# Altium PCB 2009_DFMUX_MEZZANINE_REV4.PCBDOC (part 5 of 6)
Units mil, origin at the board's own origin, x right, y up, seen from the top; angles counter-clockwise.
Board outline 4922.86 x 3627.76 mil, 6 copper layers (Top Layer, Internal Plane 1, Mid-Layer 1, Internal Plane 2, Mid-Layer 2, Bottom Layer); 519 components, 606 nets, 2175 pads, 757 vias.
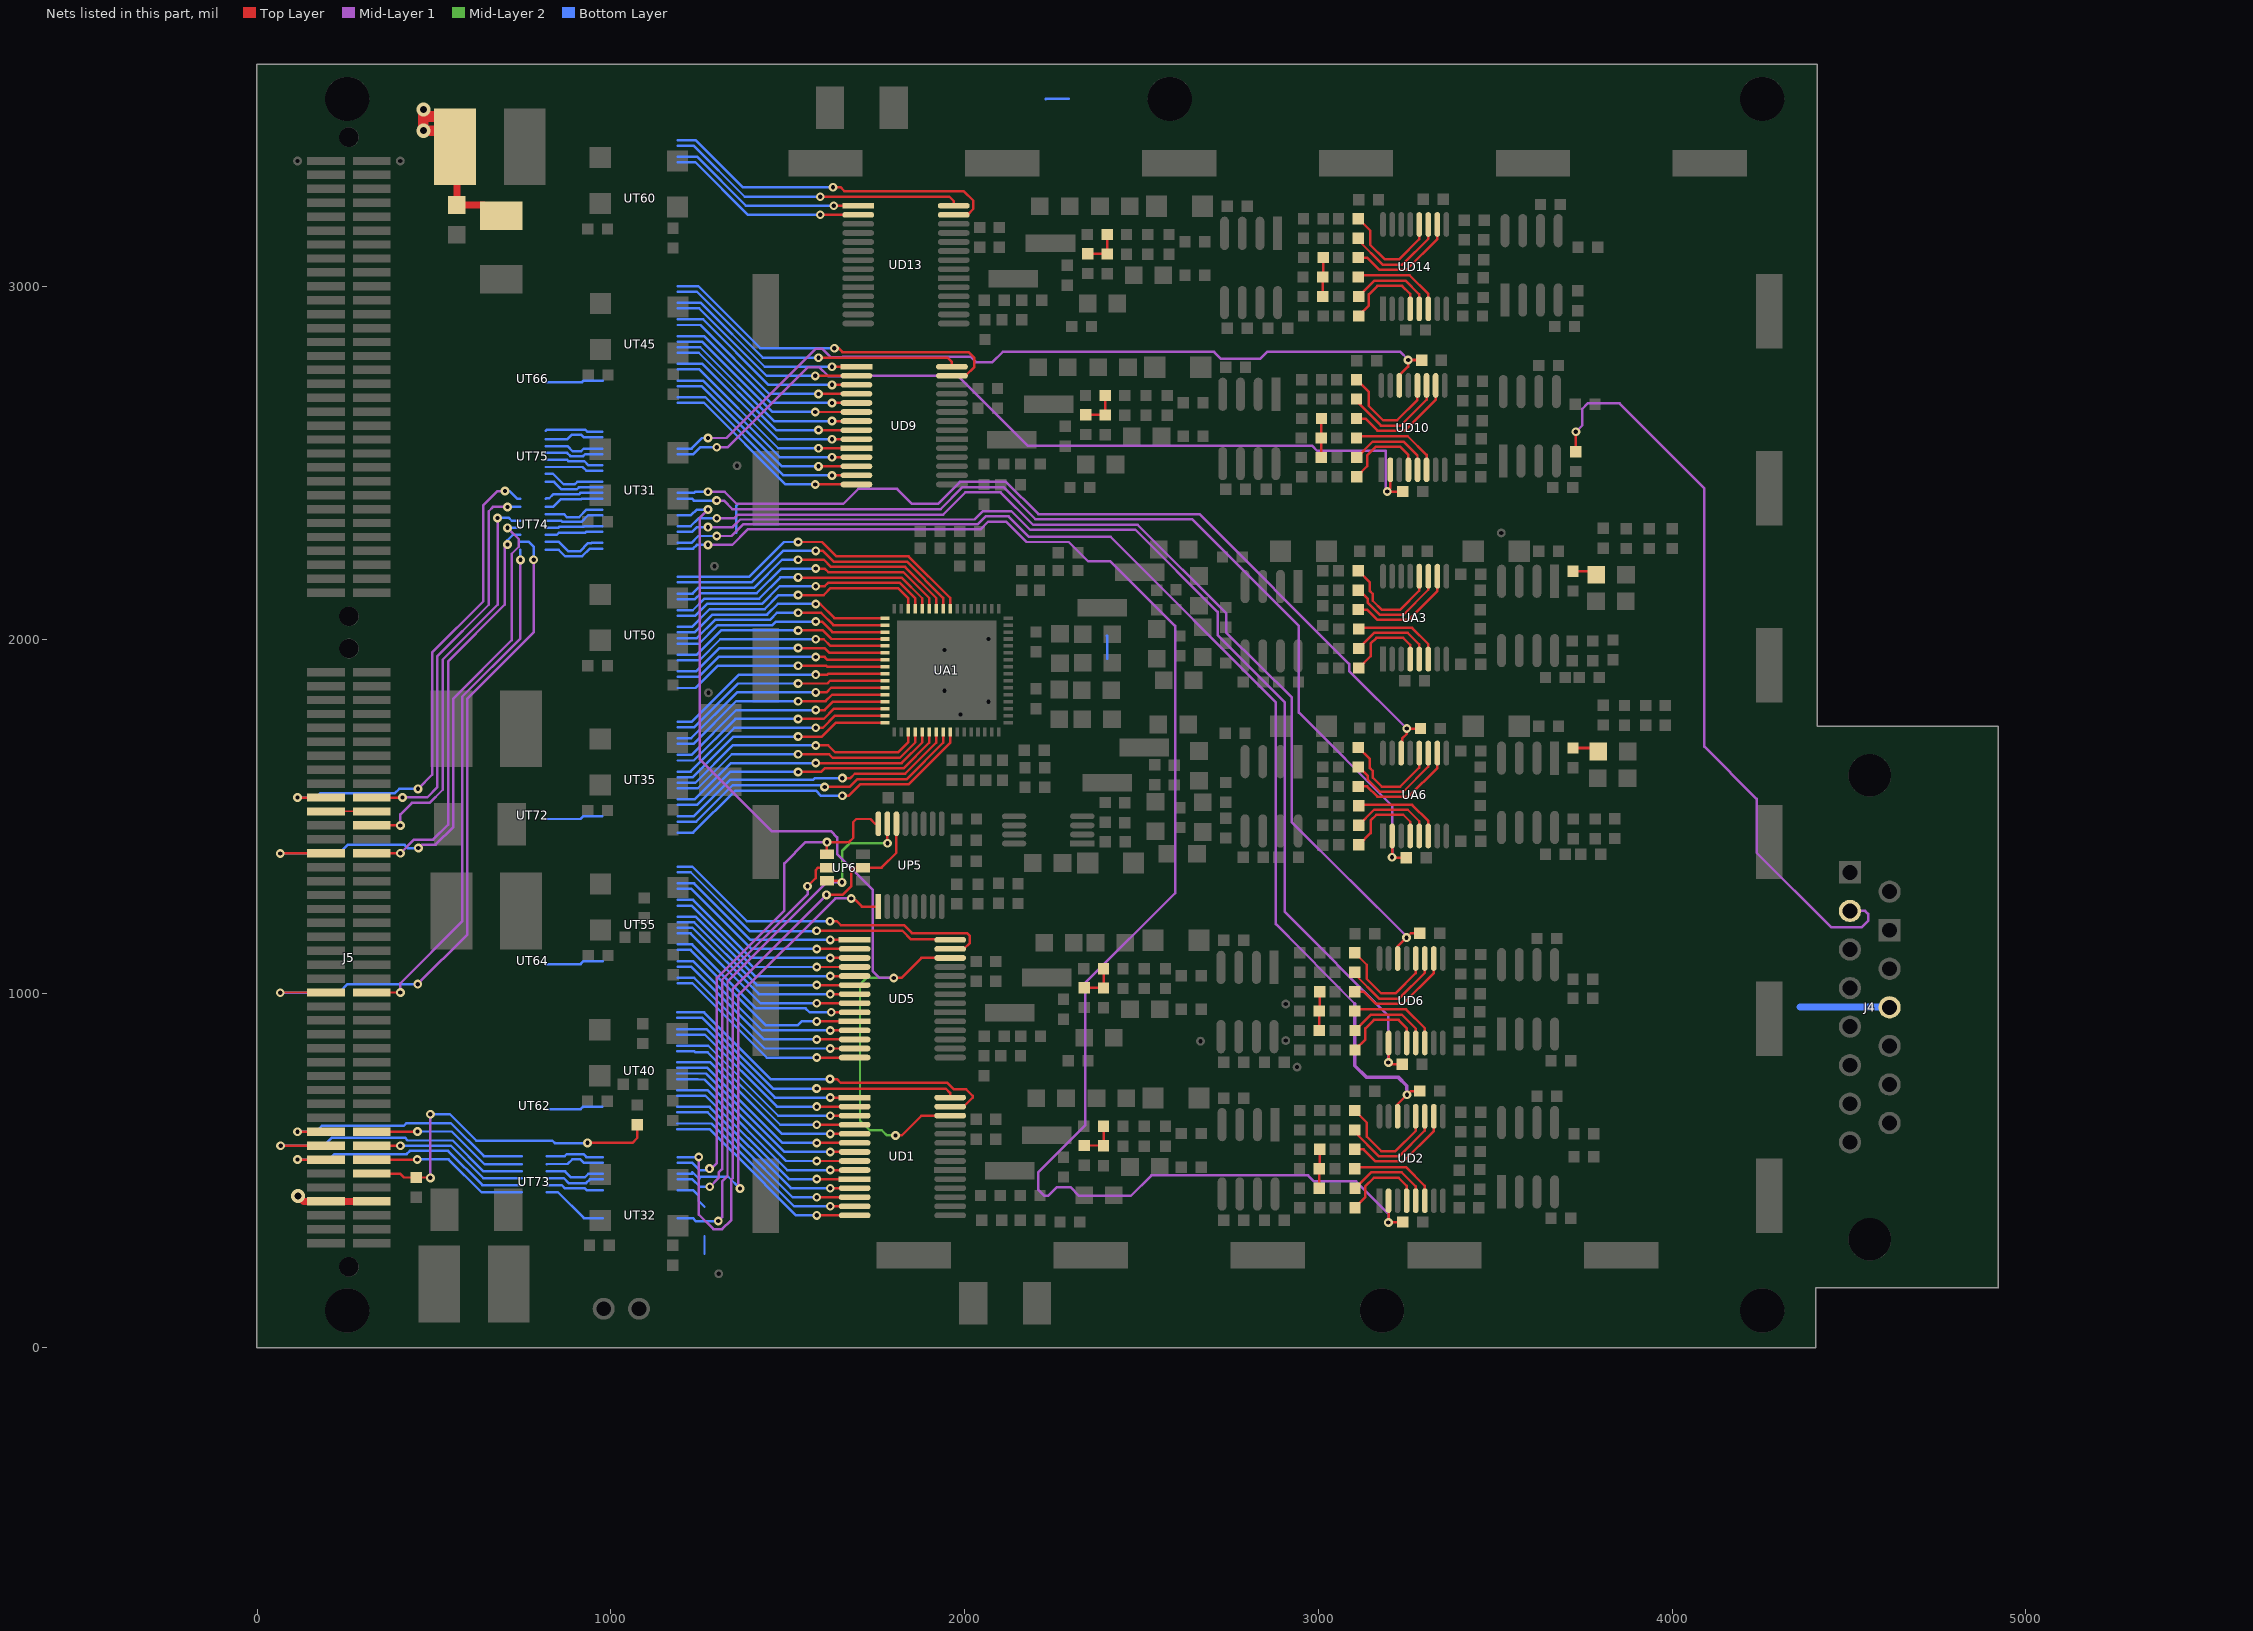
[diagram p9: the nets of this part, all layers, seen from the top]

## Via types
v1: diameter 25, hole 12, Top Layer to Bottom Layer, 692 vias
v2: diameter 40, hole 20, Top Layer to Bottom Layer, 39 vias
v3: diameter 35, hole 20, Top Layer to Bottom Layer, 23 vias
v4: diameter 22, hole 12, Top Layer to Bottom Layer, 3 vias

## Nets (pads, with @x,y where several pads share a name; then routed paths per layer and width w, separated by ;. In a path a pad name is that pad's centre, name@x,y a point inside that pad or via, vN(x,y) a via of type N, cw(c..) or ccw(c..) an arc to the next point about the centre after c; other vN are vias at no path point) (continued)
N840871_10471: UT45.30 UT66.5 | length 163.7
  Bottom Layer w7: UT66.5@815.13,2728.37 918.63,2728.37 923.03,2732.77 UT45.30@977.03,2732.77
N840871_10667: UT55.30 UT64.5 | length 165.4
  Bottom Layer w7: UT64.5@815.13,1083.37 914.63,1083.37 923.03,1091.77 UT55.30@977.03,1091.77
N840871_10863: UT40.30 UT62.5 | length 157.6
  Bottom Layer w7: UT62.5@820.13,673.37 914.63,673.37 921.03,679.77 UT40.30@975.03,679.77
N840871_11255: UT35.30 UT72.5 | length 164.4
  Bottom Layer w7: UT72.5@815.13,1493.37 913.63,1493.37 922.03,1501.77 UT35.30@976.03,1501.77
N867949: J5.19 UT74.16 | length 1439.7
  Top Layer w7: v1(114.33,1554.07) J5.19@194.63,1554.07
  Mid-Layer 1 w7: v1(454.63,1578.57) 494.63,1618.57 494.63,1964 639.63,2109 639.63,2381 679,2420.37 v1(700.63,2420.37)
  Bottom Layer w7: v1(114.33,1554.07) 166.13,1554.07 178.63,1566.57 389.63,1566.57 401.63,1578.57 v1(454.63,1578.57) ; v1(700.63,2420.37) 713.63,2420.37 735.63,2398.37 UT74.16@744.13,2398.37
N869068: J5.20 UT74.15 | length 1132.4
  Top Layer w7: J5.20@324.55,1554.07 410.93,1554.07 v1(410.63,1554.37)
  Mid-Layer 1 w7: v1(410.63,1554.37) 411.1,1554.83 481.1,1554.83 509.63,1583.37 509.63,1954 654.63,2099 654.63,2363.37 666.63,2375.37 v1(707.63,2375.37)
  Bottom Layer w7: v1(707.63,2375.37) UT74.15@744.13,2375.37
N870193: RA31.2 UA6.14 UT31.13 | length 2553
  Top Layer w7: UA6.14@3233.82,1679.68 3236.63,1682.5 3236.63,1721 3249.63,1734 v1(3249.63,1749) RA31.2@3288.63,1749
  Mid-Layer 1 w7: v1(1274.27,2418.37) 1321.27,2418.37 1355.63,2384 1656.86,2384 1699.27,2426.41 1809.27,2426.41 1851.68,2384 1924.36,2384 1986.77,2446.41 2116.77,2446.41 2208.18,2355 2663.63,2355 3086.63,1932 3086.63,1912 v1(3249.63,1749)
  Bottom Layer w7: UT31.13@1188.63,2414.97 1235.53,2414.97 1239.13,2418.37 v1(1274.27,2418.37)
N871887: RA55.2 UA6.2 UT31.14 | length 2821.3
  Top Layer w7: UA6.2@3208.23,1445.43 v1(3208.23,1385.4) 3209.63,1384 RA55.2@3248.63,1384
  Mid-Layer 1 w7: v1(1299,2393.37) 1319.27,2393.37 1343.63,2369 1931.86,2369 1994.27,2431.41 2109.27,2431.41 2199.68,2341 2643,2341 2945,2039.37 2945,1794 3208.63,1530 3208.63,1385.8 v1(3208.23,1385.4)
  Bottom Layer w7: UT31.14@1188.63,2399.27 1228.73,2399.27 1234.63,2393.37 v1(1299,2393.37)
N888717: UD1.26 UD5.26 UT31.17 | length 2741.6
  Top Layer w7: v1(1799.63,1044) 1821.27,1044 1877.9,1100.63 UD5.26@1959.03,1100.63 ; v1(1804.63,599) 1822.27,599 1877.9,654.63 UD1.26@1959.03,654.63
  Mid-Layer 1 w7: v1(1274.63,2368) 1250.63,2344 1250.63,1662.55 1454.27,1458.91 1621.77,1458.91 1639.27,1441.41 1639.27,1394.36 1739.63,1294 1739.63,1064 1759.27,1044 v1(1799.63,1044)
  Mid-Layer 2 w7: v1(1799.63,1044) 1722.25,1044 1704.13,1025.88 1704.13,640.5 1731.63,613.5 1765.5,613.5 1780,599 v1(1804.63,599)
  Bottom Layer w7: UT31.17@1188.63,2352.17 1226.3,2352.17 1242.93,2368 v1(1274.63,2368)
N890448: J5.24 UT74.13 | length 1160.3
  Top Layer w7: J5.24@324.55,1475.33 v1(404.85,1475.33)
  Mid-Layer 1 w7: v1(404.85,1475.33) 404.85,1506.22 437.63,1539 487.63,1539 524.63,1576 524.63,1944 679.63,2099 v1(679.63,2344.37)
  Bottom Layer w7: v1(679.63,2344.37) 711.63,2344.37 719.63,2336.37 UT74.13@744.13,2336.37
N891610: RD31.2 UD6.14 UT31.19 | length 2972.9
  Top Layer w7: UD6.14@3223.8,1099.02 3223.8,1133.17 v1(3248.63,1158) 3261.07,1170.43 RD31.2@3286.63,1170.43
  Mid-Layer 1 w7: v1(1299.27,2343.37) 1348,2343.37 1358.63,2354 1939.36,2354 2001.77,2416.41 2101.77,2416.41 2193.18,2325 2488.63,2325 2739.63,2074 2739.63,2019.37 2925,1836.37 2925,1484 3248.63,1162 v1(3248.63,1158)
  Bottom Layer w7: UT31.19@1188.63,2320.77 1225.4,2320.77 1248,2343.37 v1(1299.27,2343.37)
N892778: RD59.2 UD6.2 UT31.20 | length 3239
  Top Layer w7: v1(3197.63,805) v1@3198.23,804.4 ; UD6.2@3198.23,860.43 v1@3198.23,804.4 ; RD59.2@3236.63,800.43 3202.2,800.43 v1@3198.23,804.4
  Mid-Layer 1 w7: v1(1274.27,2318.37) 1344,2318.37 1365.63,2340 2027.86,2340 2051.77,2363.91 2131.77,2363.91 2184.68,2311 2482.63,2311 2715,2078.63 2715,2014 2905,1822.37 2905,1231 3197.63,936 3197.63,807 3196.63,806 v1(3197.63,805)
  Bottom Layer w7: UT31.20@1188.63,2305.07 1229.7,2305.07 1243,2318.37 v1(1274.27,2318.37)
N895125: RD1.2 UD2.14 UT31.22 | length 3382.3
  Top Layer w7: UD2.14@3223.8,653.02 3223.8,687.17 v1(3250.63,714) ; RD1.2@3286.63,724.43 3261.07,724.43 ; v1(3250.63,714) 3261.07,724.43 ; v1(3250.63,714) 3261.07,724.43
  Mid-Layer 1 w7: v1(1299.27,2293.37) 1341,2293.37 1373.63,2326 2036.36,2326 2059.27,2348.91 2124.27,2348.91 2182.18,2291 2413,2291 2880,1822.37 2880,1196.23 3102.63,971.23
  Mid-Layer 1 w10: 3102.63,971.23 3102.63,796.37 3135,764 3225,764 3250,739 3250,714.63 v1(3250.63,714)
  Bottom Layer w7: UT31.22@1188.63,2273.67 1227.53,2273.67 1246.83,2293.37 v1(1299.27,2293.37)
N896305: RD29.2 UD2.2 UT31.23 | length 4530.2
  Top Layer w7: v1(3197.63,353) 3198.03,352.6 v1@3198.23,352.6 ; UD2.2@3198.23,414.43 v1@3198.23,352.6 ; RD29.2@3238.63,355 RD29.2@3238.63,354 3199.63,354 v1@3198.23,352.6
  Mid-Layer 1 w7: v1(1274.27,2268.37) 1343,2268.37 1386.63,2312 2044.86,2312 2066.77,2333.91 2116.77,2333.91 2174.27,2276.41 2294.36,2276.41 2349.27,2221.5 2412.13,2221.5 2594.63,2039 2594.63,1283.63 2340.63,1029.63 2340.63,627 2207.63,494 2207.63,446 2225.63,428 2235.63,428 2260.63,453 2298.63,453 2323.63,428 2469.63,428 2527.63,486 2970.63,486 2987.63,469 3106.63,469 3198.63,377 3198.63,354 v1(3197.63,353)
  Bottom Layer w7: UT31.23@1188.63,2257.97 1232.6,2257.97 1243,2268.37 v1(1274.27,2268.37)
N906454: J5.27 UT74.12 | length 1628.9
  Top Layer w7: v1(65.55,1395.83) 66.32,1396.6 J5.27@194.63,1396.6
  Mid-Layer 1 w7: v1(455.73,1411.27) 455.9,1411.27 465.63,1421 504.63,1421 554.63,1471 554.63,1834 719.63,1999 719.63,2243.13 739.63,2262.93 739.63,2284.37 v1(707.63,2316.37)
  Bottom Layer w7: v1(65.55,1395.83) 231.2,1395.83 255.63,1420.27 416.63,1420.27 425.63,1411.27 v1(455.73,1411.27) ; v1(707.63,2316.37) UT74.12@744.13,2316.37
N908856: J5.28 UT74.11 | length 1165.1
  Top Layer w7: J5.28@324.55,1396.6 v1(404.85,1396.6)
  Mid-Layer 1 w7: v1(404.85,1396.6) 443.25,1435 497.63,1435 539.63,1477 539.63,1939 699.63,2099 699.63,2261.37 v1(707.63,2269.37)
  Bottom Layer w7: v1(707.63,2269.37) 707.63,2281.37 722.63,2296.37 UT74.11@744.13,2296.37
N958957: J5.47 UT74.10 | length 1943.7
  Top Layer w7: v1(65.55,1002.17) 66.32,1002.93 J5.47@194.63,1002.93
  Mid-Layer 1 w7: v1(453.87,1026.6) 594.63,1167.37 594.63,1834 781.63,2021 v1(781.63,2226.37)
  Bottom Layer w7: v1(65.55,1002.17) 231.2,1002.17 255.63,1026.6 v1(453.87,1026.6) ; UT74.10@744.13,2277.37 767.63,2277.37 781.63,2263.37 v1(781.63,2226.37)
N960349: J5.48 UT74.9 | length 1472.3
  Top Layer w7: J5.48@324.55,1002.93 v1(404.85,1002.93)
  Mid-Layer 1 w7: v1(404.85,1002.93) 404.85,1029.22 579.63,1204 579.63,1839 744.13,2003.5 v1(744.13,2225.87)
  Bottom Layer w7: v1(744.13,2225.87) UT74.9@744.13,2254.37
N995552: J5.74 RP1.1 RP4.1 | length 1012.3
  Top Layer w7: J5.74@324.55,491.17 403.47,491.17 414.63,480 RP4.1@449.63,480 488.63,480 v1(489.63,479) ; v1(933.63,578) 1060.63,578 1074.63,592 RP1.1@1074.63,629
  Mid-Layer 1 w7: v1(489.63,479) v1(489.63,659)
  Bottom Layer w7: v1(489.63,659) 544.63,659 619.63,584 834.63,584 841.63,577 932.63,577 v1(933.63,578)
N1002964: CP12.1 J5.77 J5.78 LP3.1 RP13.1 | length 738.8
  Top Layer w7: LP3.1@559.63,3394 LP3.1@564.63,3389 ; CP12.1@640.63,3229 671.63,3198 688.63,3198 CP12.1@689.63,3199
  Top Layer w10: LP3.1@514.63,3439 LP3.1@559.63,3394
  Top Layer w20: v2(115.7,427.82) 131.08,412.43 J5.77@194.63,412.43 J5.78@324.55,412.43 ; LP3.1@564.63,3389 RP13.1@564.63,3229 CP12.1@640.63,3229
  Top Layer w30: v2(470,3499) 470,3479 ; LP3.1@514.63,3439 v2(470,3439) 470,3479 ; LP3.1@520,3479 470,3479
N1115828: UP5.15 UP6.6 UT32.13 | length 1573.1
  Top Layer w7: UP6.6@1610.67,1318.37 1649.63,1318.37 v1(1653.63,1314.37) ; UP5.15@1781.52,1480.05 1781.52,1424.48 1781.63,1424.37 v1(1781.63,1425)
  Mid-Layer 1 w7: v1(1303.63,357) 1314.63,368 1314.63,469 1329.63,484 1329.63,1034 1610.63,1315 1652.63,1315 1653.63,1314 v1(1653.63,1314.37)
  Mid-Layer 2 w7: v1(1653.63,1314.37) 1653.63,1403.27 1675.36,1425 v1(1781.63,1425)
  Bottom Layer w7: UT32.13@1189.63,364.97 1231.67,364.97 1239.63,357 v1(1303.63,357)
N1144411: UT32.36 UT73.6 | length 188.3
  Bottom Layer w7: UT73.6@819.13,438.37 850.27,438.37 923.67,364.97 UT32.36@977.03,364.97
N1162483: UT32.47 UT73.1 | length 163.7
  Bottom Layer w7: UT73.1@819.13,540.37 869.63,540.37 875.27,546 922.63,546 930.97,537.67 UT32.47@977.03,537.67
N1165605: UT32.46 UT73.2 | length 167.2
  Bottom Layer w7: UT73.2@819.13,517.37 877.63,518.37 890.63,531.37 913.63,531.37 923.03,521.97 UT32.46@977.03,521.97
N1167954: UT32.44 UT73.3 | length 169.2
  Bottom Layer w7: UT73.3@819.13,497.37 870.63,497.37 887.63,480.37 926,480.37 936.2,490.57 UT32.44@977.03,490.57
N1236272: CA46.2 RA13.2 | length 70.1
  Top Layer w7: RA13.2@3719.63,2194 3775.63,2194 CA46.2@3785.63,2184
N1241817: CA48.2 RA36.2 | length 75.1
  Top Layer w8: RA36.2@3719.63,1694 3780.63,1694 CA48.2@3790.63,1684
N1340990: J4.2 RD78.2 | length 2154.9
  Top Layer w7: RD78.2@3727.63,2531.43 v1(3727.63,2587.93)
  Mid-Layer 1 w7: v1(3727.63,2587.93) 3746.13,2606.43 3746.13,2652.93 3761.13,2667.93 3851.13,2667.93 4091.13,2427.93 4091.13,1697.93 4238.63,1550.43 4238.63,1397.93 4449,1187.57 4536.13,1187.57 4553.63,1205.07 4553.63,1225.07 4545.2,1233.5 J4.2@4502.5,1233.5
N1421104: RD61.2 UD10.14 UT31.5 | length 2397.7
  Top Layer w7: UD10.14@3228.8,2719.02 3226.63,2721.18 3226.63,2745.43 3253.63,2772.43 v1@3253.63,2790.43 ; v1@3253.63,2790.43 RD61.2@3291.63,2790.43 3291.07,2791 v1(3253.63,2791) v1@3253.63,2790.43
  Mid-Layer 1 w7: v1(1274.27,2570.37) 1327,2570.37 1579.63,2823 1596.63,2823 1620.63,2799 1654.63,2799 1655.63,2800 2016.63,2800 2031.63,2785 2078.63,2785 2107.63,2814 2705,2814 2725,2794 2835,2794 2855,2814 3231.63,2814 3252.63,2793 3252.63,2792 v1(3253.63,2791)
  Bottom Layer w7: UT31.5@1188.63,2540.57 1226.83,2540.57 1227.03,2540.37 1228,2540.37 1258,2570.37 v1(1274.27,2570.37)
N1428417: RD89.2 UD10.2 UT31.6 | length 2434.5
  Top Layer w7: UD10.2@3203.23,2480.43 3203.23,2427.6 v1(3194.63,2419) RD89.2@3238.63,2419 3238.63,2420 RD89.2@3233.63,2420
  Mid-Layer 1 w7: v1(1299.27,2544.37) 1331,2544.37 1557.63,2771 1588.63,2771 1614.63,2745 1704.63,2745 1705.63,2746 1980.63,2746 2177.63,2549 2981.63,2549 2996.63,2534 3190.63,2534 3190.63,2423 v1(3194.63,2419)
  Bottom Layer w7: UT31.6@1188.63,2524.87 1233.1,2524.87 1253.1,2544.37 v1(1299.27,2544.37)
N2077430: DP1.2 RP8.1 | length 78.8
  Bottom Layer w7: DP1.2@1354.63,2303 1354.63,2379 RP8.1@1356.63,2381
N2078571: DP3.2 RP17.1 | length 67.4
  Bottom Layer w7: DP3.2@2228.63,3529 2228.63,3528 2229.63,3529 RP17.1@2294.63,3529
N2311501: UT32.43 UT73.4 | length 168
  Bottom Layer w7: UT73.4@819.13,478.37 866.63,478.37 880.63,464.37 930,464.37 940.5,474.87 UT32.43@977.03,474.87
N2314699: UT32.41 UT73.5 | length 164.1
  Bottom Layer w7: UT73.5@819.13,458.37 861,458.37 869.37,450 925.63,450 932.17,443.47 UT32.41@977.03,443.47
N2484141: J5.67 UT73.16 | length 763
  Top Layer w7: v1(114.33,609.27) J5.67@194.63,609.27
  Bottom Layer w7: v1(114.33,609.27) 166.13,609.27 182.63,626 414.58,626 422.53,633.77 547.37,633.77 640.77,540.37 UT73.16@748.13,540.37
N2488507: J5.68 UT73.15 | length 466.3
  Top Layer w7: J5.68@324.55,609.27 452.87,609.27 v1(453.63,610.03)
  Bottom Layer w7: v1@449.63,610.03 v1(453.63,610.03) 550.1,610.03 642.77,517.37 UT73.15@748.13,517.37
N2489600: J5.69 UT73.14 | length 858.9
  Top Layer w7: v1(66.55,569.9) J5.69@194.63,569.9
  Bottom Layer w7: v1(66.55,569.9) 188.77,569.9 212.2,593 417.63,593 425.63,584.57 553.07,584.57 640.27,497.37 UT73.14@748.13,497.37
N2492888: J5.71 UT73.12 | length 764.3
  Top Layer w7: v1(114.33,530.53) J5.71@194.63,530.53
  Bottom Layer w7: v1(114.33,530.53) 203.63,530.53 219.13,546 422.67,546 431.63,555.03 540.1,555.03 636.77,458.37 UT73.12@748.13,458.37
N2615723: J5.70 UT73.13 | length 464.2
  Top Layer w7: J5.70@324.55,569.9 v1(404.85,569.9) v1@406.17,569.9
  Bottom Layer w7: v1@403.85,568.9 v1(404.85,569.9) 547.73,569.9 639.27,478.37 UT73.13@748.13,478.37
N2902454: J5.72 UT73.11 | length 463
  Top Layer w7: J5.72@324.55,530.53 452.87,530.53 452.87,530.77 v1(452.63,531)
  Bottom Layer w7: v1(452.63,531) 452.93,531.3 541.33,531.3 634.27,438.37 UT73.11@748.13,438.37
N3312794: J4.12 RG1.2 | length 251.7
  Bottom Layer w20: RG1.2@4362,962 J4.12@4613.7,962
N3409536: J5.21 J5.22 | length 129.9
  Top Layer w4: J5.21@194.63,1514.7 J5.22@324.55,1514.7
N4032631: RA39.1 UA6.10 | length 311
  Top Layer w7: RA39.1@3112.63,1585.43 3137.63,1585.43 3166.63,1556.43 3254.63,1556.43 3336.18,1637.98 UA6.10@3336.18,1679.68
N4033590: RA26.2 UA3.6 | length 259.3
  Top Layer w7: RA26.2@3113.63,2030.43 3116.63,2033.43 3264.63,2033.43 3310.63,1987.43 UA3.6@3310.63,1945.43
N4033750: RA45.2 UA6.5 | length 244.6
  Top Layer w7: RA45.2@3113.63,1475.43 3157.63,1519.43 3252.63,1519.43 3285.03,1487.03 UA6.5@3285.03,1445.43
N4034511: RA14.1 UA3.10 | length 311
  Top Layer w7: RA14.1@3112.63,2085.43 3137.63,2085.43 3166.63,2056.43 3254.63,2056.43 3336.18,2137.98 UA3.10@3336.18,2179.68
N4034991: RA38.1 UA6.11 | length 301.1
  Top Layer w7: RA38.1@3112.63,1640.43 3114.63,1640.43 3139.63,1615.43 3139.63,1604.43 3173.63,1570.43 3239.63,1570.43 3310.58,1641.38 UA6.11@3310.58,1679.68
N4037191: RA16.1 UA3.11 | length 301.1
  Top Layer w7: RA16.1@3112.63,2140.43 3114.63,2140.43 3139.63,2115.43 3139.63,2104.43 3173.63,2070.43 3239.63,2070.43 3310.58,2141.38 UA3.11@3310.58,2179.68
N4040194: RA24.2 UA3.4 | length 250.5
  Top Layer w7: RA24.2@3113.63,1920.43 3114.63,1920.43 3147.63,1953.43 3147.63,1989.43 3163.63,2005.43 3239.63,2005.43 3259.43,1985.63 UA3.4@3259.43,1945.43
N4040195: RA25.2 UA3.5 | length 244.6
  Top Layer w7: RA25.2@3113.63,1975.43 3157.63,2019.43 3252.63,2019.43 3285.03,1987.03 UA3.5@3285.03,1945.43
N4040351: RA37.1 UA6.12 | length 307.5
  Top Layer w7: RA37.1@3112.63,1695.43 3145.63,1662.43 3145.63,1637.43 3153.63,1629.43 3153.63,1610.43 3179.63,1584.43 3230.63,1584.43 3285,1638.8 UA6.12@3285,1679.68
N4043354: RA50.2 UA6.4 | length 250.5
  Top Layer w7: RA50.2@3113.63,1420.43 3114.63,1420.43 3147.63,1453.43 3147.63,1489.43 3163.63,1505.43 3239.63,1505.43 3259.43,1485.63 UA6.4@3259.43,1445.43
N4043356: RA48.2 UA6.6 | length 259.3
  Top Layer w7: RA48.2@3113.63,1530.43 3116.63,1533.43 3264.63,1533.43 3310.63,1487.43 UA6.6@3310.63,1445.43
N5320690: RD114.2 UD14.6 | length 264
  Top Layer w7: RD114.2@3112.63,3025.43 3117.63,3030.43 3257.63,3030.43 3310.63,2977.43 UD14.6@3310.63,2935.43
N5320690_5462: RD84.2 UD10.6 | length 264
  Top Layer w7: RD84.2@3107.63,2570.43 3112.63,2575.43 3252.63,2575.43 3305.63,2522.43 UD10.6@3305.63,2480.43
N5320690_5910: RD54.2 UD6.6 | length 264
  Top Layer w7: RD54.2@3102.63,950.43 3107.63,955.43 3247.63,955.43 3300.63,902.43 UD6.6@3300.63,860.43
N5320690_6358: RD24.2 UD2.6 | length 264
  Top Layer w7: RD24.2@3102.63,504.43 3107.63,509.43 3247.63,509.43 3300.63,456.43 UD2.6@3300.63,414.43
N5321451: RD102.2 RD105.1 RD107.1 | length 110.4
  Top Layer w7: RD107.1@3012.63,2970.43 RD105.1@3012.63,3025.43 3013.63,3026.43 RD102.2@3013.63,3080.43
N5321451_5458: RD72.2 RD75.1 RD77.1 | length 110.4
  Top Layer w7: RD77.1@3007.63,2515.43 RD75.1@3007.63,2570.43 3008.63,2571.43 RD72.2@3008.63,2625.43
N5321451_5906: RD42.2 RD45.1 RD47.1 | length 110.4
  Top Layer w7: RD47.1@3002.63,895.43 RD45.1@3002.63,950.43 3003.63,951.43 RD42.2@3003.63,1005.43
N5321451_6354: RD12.2 RD15.1 RD17.1 | length 110.4
  Top Layer w7: RD17.1@3002.63,449.43 RD15.1@3002.63,504.43 3003.63,505.43 RD12.2@3003.63,559.43
N5321931: RD97.1 UD14.10 | length 314.5
  Top Layer w7: RD97.1@3112.63,3080.43 3137.63,3080.43 3171.63,3046.43 3249.63,3046.43 3336.13,3132.93 UD14.10@3336.13,3174.02
N5321931_5455: RD67.1 UD10.10 | length 314.5
  Top Layer w7: RD67.1@3107.63,2625.43 3132.63,2625.43 3166.63,2591.43 3244.63,2591.43 3331.13,2677.93 UD10.10@3331.13,2719.02
N5321931_5903: RD37.1 UD6.10 | length 314.5
  Top Layer w7: RD37.1@3102.63,1005.43 3127.63,1005.43 3161.63,971.43 3239.63,971.43 3326.13,1057.93 UD6.10@3326.13,1099.02
N5321931_6351: RD7.1 UD2.10 | length 314.5
  Top Layer w7: RD7.1@3102.63,559.43 3127.63,559.43 3161.63,525.43 3239.63,525.43 3326.13,611.93 UD2.10@3326.13,653.02
N5323010: RD100.2 RD101.1 RD106.1 | length 110
  Top Layer w7: RD100.2@2347.63,3091.43 RD106.1@2402.63,3091.43 ; RD106.1@2402.63,3090.43 RD106.1@2402.63,3091.43 ; RD101.1@2402.63,3145.43 RD106.1@2402.63,3091.43
N5323010_5461: RD70.2 RD71.1 RD76.1 | length 110
  Top Layer w7: RD70.2@2342.63,2636.43 RD76.1@2397.63,2636.43 ; RD76.1@2397.63,2635.43 RD76.1@2397.63,2636.43 ; RD71.1@2397.63,2690.43 RD76.1@2397.63,2636.43
N5323010_5909: RD40.2 RD41.1 RD46.1 | length 110
  Top Layer w7: RD40.2@2337.63,1016.43 RD46.1@2392.63,1016.43 ; RD46.1@2392.63,1015.43 RD46.1@2392.63,1016.43 ; RD41.1@2392.63,1070.43 RD46.1@2392.63,1016.43
N5323010_6357: RD10.2 RD11.1 RD16.1 | length 110
  Top Layer w7: RD10.2@2337.63,570.43 RD16.1@2392.63,570.43 ; RD16.1@2392.63,569.43 RD16.1@2392.63,570.43 ; RD11.1@2392.63,624.43 RD16.1@2392.63,570.43
N5323331: RD96.1 UD14.11 | length 303.4
  Top Layer w7: RD96.1@3112.63,3135.43 3112.63,3129.43 3181.63,3060.43 3237.63,3060.43 3310.55,3133.35 UD14.11@3310.55,3174.02
N5323331_5463: RD66.1 UD10.11 | length 303.4
  Top Layer w7: RD66.1@3107.63,2680.43 3107.63,2674.43 3176.63,2605.43 3232.63,2605.43 3305.55,2678.35 UD10.11@3305.55,2719.02
N5323331_5911: RD36.1 UD6.11 | length 303.4
  Top Layer w7: RD36.1@3102.63,1060.43 3102.63,1054.43 3171.63,985.43 3227.63,985.43 3300.55,1058.35 UD6.11@3300.55,1099.02
N5323331_6359: RD6.1 UD2.11 | length 303.4
  Top Layer w7: RD6.1@3102.63,614.43 3102.63,608.43 3171.63,539.43 3227.63,539.43 3300.55,612.35 UD2.11@3300.55,653.02
N5324691: RD95.1 UD14.12 | length 308.4
  Top Layer w7: RD95.1@3112.63,3190.43 3146.63,3156.43 3146.63,3116.43 3187.63,3075.43 3227.63,3075.43 3284.97,3132.77 UD14.12@3284.97,3174.02
N5324691_5459: RD65.1 UD10.12 | length 308.4
  Top Layer w7: RD65.1@3107.63,2735.43 3141.63,2701.43 3141.63,2661.43 3182.63,2620.43 3222.63,2620.43 3279.97,2677.77 UD10.12@3279.97,2719.02
N5324691_5907: RD35.1 UD6.12 | length 308.4
  Top Layer w7: RD35.1@3102.63,1115.43 3136.63,1081.43 3136.63,1041.43 3177.63,1000.43 3217.63,1000.43 3274.97,1057.77 UD6.12@3274.97,1099.02
N5324691_6355: RD5.1 UD2.12 | length 308.4
  Top Layer w7: RD5.1@3102.63,669.43 3136.63,635.43 3136.63,595.43 3177.63,554.43 3217.63,554.43 3274.97,611.77 UD2.12@3274.97,653.02
N5327690: RD113.2 UD14.4 | length 251.4
  Top Layer w7: RD113.2@3113.63,2915.43 3113.63,2916.43 3142.63,2945.43 3142.63,2976.43 3166.63,3000.43 3236.63,3000.43 3259.43,2977.63 UD14.4@3259.43,2935.43
N5327690_5457: RD83.2 UD10.4 | length 251.4
  Top Layer w7: RD83.2@3108.63,2460.43 3108.63,2461.43 3137.63,2490.43 3137.63,2521.43 3161.63,2545.43 3231.63,2545.43 3254.43,2522.63 UD10.4@3254.43,2480.43
N5327690_5905: RD53.2 UD6.4 | length 251.4
  Top Layer w7: RD53.2@3103.63,840.43 3103.63,841.43 3132.63,870.43 3132.63,901.43 3156.63,925.43 3226.63,925.43 3249.43,902.63 UD6.4@3249.43,860.43
N5327690_6353: RD23.2 UD2.4 | length 251.4
  Top Layer w7: RD23.2@3103.63,394.43 3103.63,395.43 3132.63,424.43 3132.63,455.43 3156.63,479.43 3226.63,479.43 3249.43,456.63 UD2.4@3249.43,414.43
N5329095: RD111.2 UD14.5 | length 247
  Top Layer w7: RD111.2@3113.63,2970.43 3158.63,3015.43 3245.63,3015.43 3285.03,2976.03 UD14.5@3285.03,2935.43
N5329095_5456: RD81.2 UD10.5 | length 247
  Top Layer w7: RD81.2@3108.63,2515.43 3153.63,2560.43 3240.63,2560.43 3280.03,2521.03 UD10.5@3280.03,2480.43
N5329095_5904: RD51.2 UD6.5 | length 247
  Top Layer w7: RD51.2@3103.63,895.43 3148.63,940.43 3235.63,940.43 3275.03,901.03 UD6.5@3275.03,860.43
N5329095_6352: RD21.2 UD2.5 | length 247
  Top Layer w7: RD21.2@3103.63,449.43 3148.63,494.43 3235.63,494.43 3275.03,455.03 UD2.5@3275.03,414.43
N5706160: DP2.2 RP12.1 | length 65.4
  Bottom Layer w7: DP2.2@2401.63,2012 2402.63,2011 RP12.1@2402.63,1947
N5982770: DP5.2 RP35.1 | length 49.4
  Bottom Layer w7: RP35.1@1264.63,264 DP5.2@1264.63,313.37
N40401912: RA15.1 UA3.12 | length 307.5
  Top Layer w7: RA15.1@3112.63,2195.43 3145.63,2162.43 3145.63,2137.43 3153.63,2129.43 3153.63,2110.43 3179.63,2084.43 3230.63,2084.43 3285,2138.8 UA3.12@3285,2179.68
N55995526: UT31.26 UT74.8 | length 177.6
  Bottom Layer w7: UT74.8@815.13,2254.37 852.27,2254.37 870.63,2236 918.63,2236 940.6,2257.97 UT31.26@976.03,2257.97
N55995527: UT31.27 UT74.7 | length 182
  Bottom Layer w7: UT74.7@815.13,2277.37 852.27,2277.37 879.63,2250 912.63,2250 935.63,2273 944.63,2273 945.3,2273.67 UT31.27@976.03,2273.67
N55995528: UT31.29 UT74.6 | length 164.5
  Bottom Layer w7: UT74.6@815.13,2296.37 847,2296.37 852.63,2302 918.63,2302 919.63,2303 927.63,2303 929.7,2305.07 UT31.29@976.03,2305.07
N55995529: UT31.30 UT74.5 | length 163
  Bottom Layer w7: UT74.5@815.13,2316.37 851.27,2316.37 853.63,2319 922.63,2319 924.63,2321 955.63,2321 955.87,2320.77 UT31.30@976.03,2320.77
N55995530: UT31.32 UT74.4 | length 170.2
  Bottom Layer w7: UT74.4@815.13,2336.37 860,2336.37 863.37,2333 916.63,2333 935.63,2352 975.87,2352 UT31.32@976.03,2352.17
N55995531: UT31.33 UT74.3 | length 173
  Bottom Layer w7: UT74.3@815.13,2355.37 867,2355.37 875.37,2347 910.63,2347 931.5,2367.87 UT31.33@976.03,2367.87
N55995532: UT31.35 UT74.2 | length 171
  Bottom Layer w7: UT74.2@815.13,2375.37 836,2375.37 857.63,2397 915.63,2397 917.63,2399 927.63,2399 927.63,2399.27 UT31.35@976.03,2399.27
N55995533: UT31.36 UT74.1 | length 167.8
  Bottom Layer w7: UT74.1@815.13,2398.37 816.77,2400 825.63,2400 836.63,2411 909.63,2411 913.6,2414.97 UT31.36@976.03,2414.97
N55995534: UT31.37 UT75.8 | length 172.1
  Bottom Layer w7: UT75.8@815.13,2446.37 839.27,2446.37 860.63,2425 903.63,2425 909.3,2430.67 UT31.37@976.03,2430.67
N55995535: UT31.38 UT75.7 | length 176.5
  Bottom Layer w7: UT75.7@815.13,2469.37 836.27,2469.37 866.63,2439 897.63,2439 905,2446.37 UT31.38@976.03,2446.37
N55995536: UT31.40 UT75.6 | length 165.3
  Bottom Layer w7: UT75.6@815.13,2488.37 920.27,2488.37 930.87,2477.77 UT31.40@976.03,2477.77
N55995537: UT31.41 UT75.5 | length 167.7
  Bottom Layer w7: UT75.5@815.13,2508.37 876.27,2508.37 879.63,2505 924.63,2505 936.63,2493 936.63,2493.47 UT31.41@976.03,2493.47
N55995538: UT31.43 UT75.4 | length 167.2
  Bottom Layer w7: UT75.4@815.13,2528.37 876.27,2528.37 885.63,2519 921.63,2519 927.5,2524.87 UT31.43@976.03,2524.87
N55995539: UT31.44 UT75.3 | length 170
  Bottom Layer w7: UT75.3@815.13,2547.37 877.27,2547.37 891.63,2533 915.63,2533 923.2,2540.57 UT31.44@976.03,2540.57
N55995540: UT31.46 UT75.2 | length 169.5
  Bottom Layer w7: UT75.2@815.13,2567.37 877,2567.37 889.63,2580 915.63,2580 923.67,2571.97 UT31.46@976.03,2571.97
N55995545: UT31.47 UT75.1 | length 164.8
  Bottom Layer w7: UT75.1@815.13,2590.37 819.13,2594 927.35,2594 933.97,2587.67 UT31.47@976.03,2587.67
POWER_DATA0: UP5.14 UP6.2 UT32.2 | length 1725.8
  Top Layer w7: v1(1609.63,1279) 1654.63,1279 1679.63,1304 1679.63,1347.07 1688.43,1355.87 UP6.2@1712.63,1355.87 1765.13,1355.87 1807.12,1397.85 UP5.14@1807.12,1480.05
  Mid-Layer 1 w7: v1(1248.3,537.67) 1248.3,375.33 1289.63,334 1314.63,334 1339.63,359 1339.63,474 1344.63,479 1344.63,1014 v1(1609.63,1279)
  Bottom Layer w7: UT32.2@1189.63,537.67 v1(1248.3,537.67)
POWER_DATA1: UP5.16 UP6.4 UT32.3 | length 1446.2
  Top Layer w7: UP6.4@1610.63,1393.37 v1(1610.63,1428) 1673.13,1428 1685.07,1439.93 1685.07,1484.8 1693.63,1493.37 1733.63,1493.37 1746.95,1480.05 UP5.16@1755.93,1480.05
  Mid-Layer 1 w7: v1(1278.63,505) 1278.63,500 1299.63,521 1299.63,1044 1490.63,1235 1490.63,1368 1550.63,1428 v1(1610.63,1428)
  Bottom Layer w7: UT32.3@1189.63,521.97 1229.67,521.97 1250.63,501 1278.63,501 v1(1278.63,505)
POWER_DATA2: UP5.1 UT32.5 | length 1270.2
  Top Layer w7: v1(1679.63,1269) 1684.63,1264 1691.63,1264 1709.63,1246 1709.63,1245.8 UP5.1@1755.93,1245.8
  Mid-Layer 1 w7: v1(1364.63,449) 1359.63,454 1359.63,994 1634.63,1269 v1(1679.63,1269)
  Bottom Layer w7: UT32.5@1189.63,490.57 1230.03,490.57 1230.03,495.37 1248.4,477 1249.63,477 1254.63,482 1331.63,482 v1(1364.63,449)
POWER_DATA3: UP6.5 UT32.6 | length 1152
  Top Layer w7: v1(1555.93,1303.3) 1578.43,1325.8 1578.43,1348.3 1585.9,1355.77 UP6.5@1610.63,1355.77
  Mid-Layer 1 w7: v1(1279.63,454) 1304.63,479 1304.63,494 1314.63,504 1314.63,1039 1555.93,1280.3 v1(1555.93,1303.3)
  Bottom Layer w7: UT32.6@1189.63,474.87 1230.53,474.87 1251.4,454 v1(1279.63,454)
POWER_DATA4: DP5.1 UT32.8 | length 102.7
  Bottom Layer w7: UT32.8@1189.63,443.47 1233.17,443.47 1247.63,429 1247.63,414.37 DP5.1@1264.63,397.37
RECA_DATA0: UA1.41 UT35.2 | length 642.3
  Top Layer w7: v1(1579.27,1901.41) 1611.77,1901.41 1614.16,1903.8 UA1.41@1774.92,1903.8
  Bottom Layer w7: UT35.2@1188.63,1768.67 1229.03,1768.67 1361.77,1901.41 v1(1579.27,1901.41)
RECA_DATA1: UA1.42 UT35.3 | length 640.6
  Top Layer w7: v1(1529.27,1876.41) 1611.77,1876.41 1619.47,1884.11 UA1.42@1774.92,1884.11
  Bottom Layer w7: UT35.3@1188.63,1752.97 1235.83,1752.97 1359.27,1876.41 v1(1529.27,1876.41)
RECA_DATA2: UA1.43 UT35.5 | length 645.5
  Top Layer w7: v1(1579.27,1851.41) 1609.27,1851.41 1622.29,1864.43 UA1.43@1774.92,1864.43
  Bottom Layer w7: UT35.5@1188.63,1721.57 1226.93,1721.57 1356.77,1851.41 v1(1579.27,1851.41)
RECA_DATA3: UA1.44 UT35.6 | length 643.8
  Top Layer w7: v1(1529.27,1826.41) 1606.77,1826.41 1625.1,1844.74 UA1.44@1774.92,1844.74
  Bottom Layer w7: UT35.6@1188.63,1705.87 1233.73,1705.87 1354.27,1826.41 v1(1529.27,1826.41)
RECA_DATA4: UA1.45 UT35.8 | length 648.7
  Top Layer w7: v1(1579.27,1801.41) 1604.27,1801.41 1627.92,1825.06 UA1.45@1774.92,1825.06
  Bottom Layer w7: UT35.8@1188.63,1674.47 1227.33,1674.47 1354.27,1801.41 v1(1579.27,1801.41)
RECA_DATA5: UA1.46 UT35.9 | length 647
  Top Layer w7: v1(1529.27,1776.41) 1601.77,1776.41 1630.73,1805.37 UA1.46@1774.92,1805.37
  Bottom Layer w7: UT35.9@1188.63,1658.77 1234.13,1658.77 1351.77,1776.41 v1(1529.27,1776.41)
RECA_DATA6: UA1.47 UT35.11 | length 651.9
  Top Layer w7: v1(1579.27,1751.41) 1599.27,1751.41 1633.55,1785.69 UA1.47@1774.92,1785.69
  Bottom Layer w7: UT35.11@1188.63,1627.37 1225.23,1627.37 1349.27,1751.41 v1(1579.27,1751.41)
RECA_DATA7: UA1.48 UT35.12 | length 650.2
  Top Layer w7: v1(1529.27,1726.41) 1596.77,1726.41 1636.36,1766 UA1.48@1774.92,1766
  Bottom Layer w7: UT35.12@1188.63,1611.67 1232.03,1611.67 1346.77,1726.41 v1(1529.27,1726.41)
RECA_DATA8: UA1.51 UT35.13 | length 745.2
  Top Layer w7: v1(1579.27,1701.41) 1614.27,1701.41 1634.27,1681.41 1811.77,1681.41 1840.87,1710.51 UA1.51@1840.87,1739.43
  Bottom Layer w7: UT35.13@1188.63,1595.97 1238.83,1595.97 1344.27,1701.41 v1(1579.27,1701.41)
RECA_DATA9: UA1.52 UT35.14 | length 763.3
  Top Layer w7: v1(1529.27,1676.41) 1616.77,1676.41 1626.77,1666.41 1816.77,1666.41 1860.55,1710.19 UA1.52@1860.55,1739.43
  Bottom Layer w7: UT35.14@1188.63,1580.27 1245.63,1580.27 1341.77,1676.41 v1(1529.27,1676.41)
RECA_DATA10: UA1.53 UT35.16 | length 787.8
  Top Layer w7: v1(1579.27,1651.41) 1821.77,1651.41 1880.24,1709.88 UA1.53@1880.24,1739.43
  Bottom Layer w7: UT35.16@1188.63,1548.87 1236.73,1548.87 1339.27,1651.41 v1(1579.27,1651.41)
RECA_DATA11: UA1.54 UT35.17 | length 814.2
  Top Layer w7: v1(1529.27,1626.41) 1594.27,1626.41 1604.27,1636.41 1826.77,1636.41 1899.92,1709.56 UA1.54@1899.92,1739.43
  Bottom Layer w7: UT35.17@1188.63,1533.17 1243.53,1533.17 1336.77,1626.41 v1(1529.27,1626.41)
RECA_DATA12: UA1.55 UT35.19 | length 847.1
  Top Layer w7: v1(1654.27,1608.91) 1676.77,1608.91 1689.27,1621.41 1831.77,1621.41 1919.61,1709.25 UA1.55@1919.61,1739.43
  Bottom Layer w7: UT35.19@1188.63,1501.77 1234.63,1501.77 1336.77,1603.91 1571.77,1603.91 1576.77,1608.91 v1(1654.27,1608.91)
RECA_DATA13: UA1.56 UT35.20 | length 876.7
  Top Layer w7: v1(1604.27,1583.91) 1674.27,1583.91 1696.77,1606.41 1836.77,1606.41 1939.29,1708.93 UA1.56@1939.29,1739.43
  Bottom Layer w7: UT35.20@1188.63,1486.07 1241.43,1486.07 1344.27,1588.91 1594.27,1588.91 v1(1604.27,1583.91)
RECA_DATA14: UA1.57 UT35.22 | length 918.8
  Top Layer w7: v1(1654.27,1558.91) 1671.77,1558.91 1704.27,1591.41 1841.77,1591.41 1958.98,1708.62 UA1.57@1958.98,1739.43
  Bottom Layer w7: UT35.22@1188.63,1454.67 1232.53,1454.67 1351.77,1573.91 1579.27,1573.91 1594.27,1558.91 v1(1654.27,1558.91)
RECB_DATA0: UA1.24 UT50.2 | length 907.4
  Top Layer w7: v1(1529.27,2276.41) 1596.77,2276.41 1637.31,2235.87 1841.77,2235.87 1958.98,2118.66 UA1.24@1958.98,2087.85
  Bottom Layer w7: UT50.2@1188.63,2177.67 1390.53,2177.67 1489.27,2276.41 v1(1529.27,2276.41)
RECB_DATA1: UA1.25 UT50.3 | length 873.3
  Top Layer w7: v1(1579.27,2251.41) 1599.27,2251.41 1629.81,2220.87 1836.77,2220.87 1939.29,2118.34 UA1.25@1939.29,2087.85
  Bottom Layer w7: UT50.3@1188.63,2161.97 1397.33,2161.97 1486.77,2251.41 v1(1579.27,2251.41)
RECB_DATA2: UA1.26 UT50.5 | length 845.7
  Top Layer w7: v1(1529.27,2226.41) 1601.77,2226.41 1622.31,2205.87 1831.77,2205.87 1919.61,2118.03 UA1.26@1919.61,2087.85
  Bottom Layer w7: UT50.5@1188.63,2130.57 1230.93,2130.57 1246.77,2146.41 1404.27,2146.41 1484.27,2226.41 v1(1529.27,2226.41)
RECB_DATA3: UA1.27 UT50.6 | length 811.7
  Top Layer w7: v1(1579.27,2201.41) 1604.27,2201.41 1614.81,2190.87 1826.77,2190.87 1899.92,2117.71 UA1.27@1899.92,2087.85
  Bottom Layer w7: UT50.6@1188.63,2114.87 1237.73,2114.87 1254.27,2131.41 1411.77,2131.41 1481.77,2201.41 v1(1579.27,2201.41)
RECB_DATA4: UA1.28 UT50.8 | length 783.3
  Top Layer w7: v1@1529.81,2175.87 1821.77,2175.87 1880.24,2117.4 UA1.28@1880.24,2087.85
  Bottom Layer w7: UT50.8@1188.63,2083.47 1231.33,2083.47 1264.27,2116.41 1419.27,2116.41 1479.27,2176.41 v1(1529.27,2176.41)
RECB_DATA5: UA1.29 UT50.9 | length 757.9
  Top Layer w7: v1(1579.27,2151.41) 1604.27,2151.41 1613.73,2160.87 1816.77,2160.87 1860.55,2117.08 UA1.29@1860.55,2087.85
  Bottom Layer w7: UT50.9@1188.63,2067.77 1238.13,2067.77 1271.77,2101.41 1426.77,2101.41 1476.77,2151.41 v1(1579.27,2151.41)
RECB_DATA6: UA1.30 UT50.11 | length 738.6
  Top Layer w7: v1(1529.27,2126.41) 1601.77,2126.41 1621.23,2145.87 1811.77,2145.87 1840.87,2116.77 UA1.30@1840.87,2087.85
  Bottom Layer w7: UT50.11@1188.63,2036.37 1229.23,2036.37 1279.27,2086.41 1434.27,2086.41 1474.27,2126.41 v1(1529.27,2126.41)
RECB_DATA7: UA1.33 UT50.12 | length 636.4
  Top Layer w7: v1(1579.27,2101.41) 1591.77,2101.41 1631.9,2061.28 UA1.33@1774.92,2061.28
  Bottom Layer w7: UT50.12@1188.63,2020.67 1236.03,2020.67 1286.77,2071.41 1441.77,2071.41 1471.77,2101.41 v1(1579.27,2101.41)
RECB_DATA8: UA1.34 UT50.13 | length 630.3
  Top Layer w7: v1(1529.27,2076.41) 1594.27,2076.41 1629.09,2041.59 UA1.34@1774.92,2041.59
  Bottom Layer w7: UT50.13@1188.63,2004.97 1242.83,2004.97 1294.27,2056.41 1449.27,2056.41 1469.27,2076.41 v1(1529.27,2076.41)
RECB_DATA9: UA1.35 UT50.14 | length 624.3
  Top Layer w7: v1(1579.27,2051.41) 1596.77,2051.41 1626.27,2021.91 UA1.35@1774.92,2021.91
  Bottom Layer w7: UT50.14@1188.63,1989.27 1249.63,1989.27 1301.77,2041.41 1456.77,2041.41 1466.77,2051.41 v1(1579.27,2051.41)
RECB_DATA10: UA1.36 UT50.16 | length 624.7
  Top Layer w7: v1(1529.27,2026.41) 1599.27,2026.41 1623.46,2002.22 UA1.36@1774.92,2002.22
  Bottom Layer w7: UT50.16@1188.63,1957.87 1243.23,1957.87 1311.77,2026.41 v1(1529.27,2026.41)
RECB_DATA11: UA1.37 UT50.17 | length 618.6
  Top Layer w7: v1(1579.27,2001.41) 1601.77,2001.41 1620.64,1982.54 UA1.37@1774.92,1982.54
  Bottom Layer w7: UT50.17@1188.63,1942.17 1250.03,1942.17 1309.27,2001.41 v1(1579.27,2001.41)
RECB_DATA12: UA1.38 UT50.19 | length 619.1
  Top Layer w7: v1(1529.27,1976.41) 1604.27,1976.41 1617.83,1962.85 UA1.38@1774.92,1962.85
  Bottom Layer w7: UT50.19@1188.63,1910.77 1241.13,1910.77 1306.77,1976.41 v1(1529.27,1976.41)
RECB_DATA13: UA1.39 UT50.20 | length 613
  Top Layer w7: v1(1579.27,1951.41) 1604.27,1951.41 1612.51,1943.17 UA1.39@1774.92,1943.17
  Bottom Layer w7: UT50.20@1188.63,1895.07 1247.93,1895.07 1304.27,1951.41 v1(1579.27,1951.41)
RECB_DATA14: UA1.40 UT50.22 | length 613.5
  Top Layer w7: v1(1529.27,1926.41) 1609.27,1926.41 1612.2,1923.48 UA1.40@1774.92,1923.48
  Bottom Layer w7: UT50.22@1188.63,1863.67 1239.03,1863.67 1301.77,1926.41 v1(1529.27,1926.41)
TRAN1_DATA0: UD1.27 UT40.2 | length 1012.3
  Top Layer w7: v1(1619.63,758.37) 1638.63,758.37 1649.63,747.37 1951.27,747.37 1969.63,729 2004.63,729 2022.63,711 2022.63,705.37 1997.5,680.23 UD1.27@1959.03,680.23
  Bottom Layer w7: UT40.2@1187.63,946.67 1263.3,946.67 1451.6,758.37 v1(1619.63,758.37)
TRAN1_DATA1: UD1.28 UT40.3 | length 872.3
  Top Layer w7: v1(1581.63,731.37) 1946.63,731.37 1959.03,718.97 UD1.28@1959.03,705.83
  Bottom Layer w7: UT40.3@1187.63,930.97 1258.67,930.97 1458.27,731.37 v1(1581.63,731.37)
TRAN1_DATA2: UD1.1 UT40.5 | length 581.6
  Top Layer w7: v1(1620.1,705.83) UD1.1@1689.03,705.83
  Bottom Layer w7: UT40.5@1187.63,899.57 1225.83,899.57 1226.03,899.37 1270.27,899.37 1463.8,705.83 v1(1620.1,705.83)
TRAN1_DATA3: UD1.2 UT40.6 | length 585.6
  Top Layer w7: v1(1581.77,680.23) UD1.2@1689.03,680.23
  Bottom Layer w7: UT40.6@1187.63,883.87 1265.27,883.87 1469.4,680.23 v1(1581.77,680.23)
TRAN1_DATA4: UD1.3 UT40.8 | length 583.4
  Top Layer w7: v1(1620.1,654.63) UD1.3@1689.03,654.63
  Bottom Layer w7: UT40.8@1187.63,852.47 1275.27,852.47 1473,654.63 v1(1620.1,654.63)
TRAN1_DATA5: UD1.4 UT40.9 | length 590.1
  Top Layer w7: v1(1581.77,629.03) UD1.4@1689.03,629.03 UD1.4@1687.03,627.17
  Bottom Layer w7: UT40.9@1187.63,836.77 1235.43,836.77 1238.03,834 1273.27,834 1478.6,629.03 v1(1581.77,629.03)
TRAN1_DATA6: UD1.5 UT40.11 | length 585
  Top Layer w7: v1(1620.1,603.43) UD1.5@1689.03,603.43
  Bottom Layer w7: UT40.11@1187.63,805.37 1281.27,805.37 1483.2,603.43 v1(1620.1,603.43)
TRAN1_DATA7: UD1.6 UT40.12 | length 589.1
  Top Layer w7: v1(1581.77,577.83) UD1.6@1689.03,577.83
  Bottom Layer w7: UT40.12@1187.63,789.67 1272.97,789.67 1484.63,578 1581.6,578 v1(1581.77,577.83)
TRAN1_DATA8: UD1.7 UT40.13 | length 593.2
  Top Layer w7: v1(1620.1,552.23) UD1.7@1689.03,552.23
  Bottom Layer w7: UT40.13@1187.63,773.97 1268.67,773.97 1490.4,552.23 v1(1620.1,552.23)
TRAN1_DATA9: UD1.8 UT40.14 | length 597.4
  Top Layer w7: v1(1581.77,526.63) UD1.8@1689.03,526.63
  Bottom Layer w7: UT40.14@1187.63,758.27 1245.03,758.27 1245.93,757 1264.27,757 1495,526.63 v1(1581.77,526.63)
TRAN1_DATA10: UD1.9 UT40.16 | length 594.9
  Top Layer w7: v1(1620.1,501.03) UD1.9@1689.03,501.03
  Bottom Layer w7: UT40.16@1187.63,726.87 1272.77,726.87 1498.6,501.03 v1(1620.1,501.03)
TRAN1_DATA11: UD1.10 UT40.17 | length 599
  Top Layer w7: v1(1581.77,475.43) UD1.10@1689.03,475.43
  Bottom Layer w7: UT40.17@1187.63,711.17 1267.47,711.17 1503.2,475.43 v1(1581.77,475.43)
TRAN1_DATA12: UD1.11 UT40.19 | length 596.6
  Top Layer w7: v1(1620.1,449.83) UD1.11@1689.03,449.83
  Bottom Layer w7: UT40.19@1187.63,679.77 1278.87,679.77 1508.8,449.83 v1(1620.1,449.83)
TRAN1_DATA13: UD1.12 UT40.20 | length 600.7
  Top Layer w7: v1(1581.77,424.23) UD1.12@1689.03,424.23
  Bottom Layer w7: UT40.20@1187.63,664.07 1273.85,664.07 1357.55,580 ; 1357.57,580 1513.7,424.23 v1(1581.77,424.23)
TRAN1_DATA14: UD1.13 UT40.22 | length 598.3
  Top Layer w7: v1(1620.1,398.63) UD1.13@1689.03,398.63
  Bottom Layer w7: UT40.22@1187.63,632.67 1283.97,632.67 1518,398.63 v1(1620.1,398.63)
TRAN1_DATA15: UD1.14 UT40.23 | length 602.5
  Top Layer w7: v1(1581.77,373.03) UD1.14@1689.03,373.03
  Bottom Layer w7: UT40.23@1187.63,616.97 1278.92,616.97 1346.52,549 1347.63,549 1523.6,373.03 v1(1581.77,373.03)
TRAN2_DATA0: UD5.27 UT55.2 | length 988.4
  Top Layer w7: v1(1619.63,1204.37) 1638.63,1204.37 1649.63,1193.37 1828.27,1193.37 1850.63,1171 2006.63,1171 2014.63,1163 2014.63,1143.37 1997.5,1126.23 UD5.27@1959.03,1126.23
  Bottom Layer w7: UT55.2@1189.63,1358.67 1229.97,1358.67 1384.27,1204.37 v1(1619.63,1204.37)
TRAN2_DATA1: UD5.28 UT55.3 | length 849.5
  Top Layer w7: v1(1581.63,1177.37) 1824.27,1177.37 1848.63,1153 1952.43,1153 1953.27,1151.83 UD5.28@1959.03,1151.83
  Bottom Layer w7: UT55.3@1189.63,1342.97 1225.67,1342.97 1392.27,1176.37 1580.63,1176.37 v1(1581.63,1177.37)
TRAN2_DATA2: UD5.1 UT55.5 | length 565.6
  Top Layer w7: v1(1620.1,1151.83) UD5.1@1689.03,1151.83
  Bottom Layer w7: UT55.5@1189.63,1311.57 1227.83,1311.57 1228.03,1311.37 1235.03,1311.37 1394.57,1151.83 v1(1620.1,1151.83)
TRAN2_DATA3: UD5.2 UT55.6 | length 569.7
  Top Layer w7: v1(1581.77,1126.23) UD5.2@1689.03,1126.23
  Bottom Layer w7: UT55.6@1189.63,1295.87 1227.77,1295.87 1397.4,1126.23 v1(1581.77,1126.23)
TRAN2_DATA4: UD5.3 UT55.8 | length 567.3
  Top Layer w7: v1(1620.1,1100.63) UD5.3@1689.03,1100.63
  Bottom Layer w7: UT55.8@1189.63,1264.47 1232.17,1264.47 1396,1100.63 v1(1620.1,1100.63)
TRAN2_DATA5: UD5.4 UT55.9 | length 574.1
  Top Layer w7: v1(1581.77,1075.03) UD5.4@1689.03,1075.03 UD5.4@1687.03,1073.17
  Bottom Layer w7: UT55.9@1189.63,1248.77 1227.87,1248.77 1401.6,1075.03 v1(1581.77,1075.03)
TRAN2_DATA6: UD5.5 UT55.11 | length 569
  Top Layer w7: v1(1620.1,1049.43) UD5.5@1689.03,1049.43
  Bottom Layer w7: UT55.11@1189.63,1217.37 1239.27,1217.37 1407.2,1049.43 v1(1620.1,1049.43)
TRAN2_DATA7: UD5.6 UT55.12 | length 573.1
  Top Layer w7: v1(1581.77,1023.83) UD5.6@1689.03,1023.83
  Bottom Layer w7: UT55.12@1189.63,1201.67 1234.97,1201.67 1412.8,1023.83 v1(1581.77,1023.83)
TRAN2_DATA8: UD5.7 UT55.13 | length 577.2
  Top Layer w7: v1(1620.1,998.23) UD5.7@1689.03,998.23
  Bottom Layer w7: UT55.13@1189.63,1185.97 1230.67,1185.97 1418.4,998.23 v1(1620.1,998.23)
TRAN2_DATA9: UD5.8 UT55.14 | length 581.3
  Top Layer w7: v1(1581.77,972.63) UD5.8@1689.03,972.63
  Bottom Layer w7: UT55.14@1189.63,1170.27 1225.37,1170.27 1423,972.63 v1(1581.77,972.63)
TRAN2_DATA10: UD5.9 UT55.16 | length 578.9
  Top Layer w7: v1(1622.97,947.03) UD5.9@1689.03,947.03
  Bottom Layer w7: UT55.16@1189.63,1138.87 1229.77,1138.87 1410.63,958 1550.63,958 1561.6,947.03 v1(1622.97,947.03)
TRAN2_DATA11: UD5.10 UT55.17 | length 592.4
  Top Layer w7: v1(1581.77,921.43) UD5.10@1689.03,921.43
  Bottom Layer w7: UT55.17@1189.63,1123.17 1225.47,1123.17 1438.63,910 1527.63,910 1539.07,921.43 v1(1581.77,921.43)
TRAN2_DATA12: UD5.11 UT55.19 | length 580.6
  Top Layer w7: v1(1620.1,895.83) UD5.11@1689.03,895.83
  Bottom Layer w7: UT55.19@1189.63,1091.77 1231.87,1091.77 1427.8,895.83 v1(1620.1,895.83)
TRAN2_DATA13: UD5.12 UT55.20 | length 584.7
  Top Layer w7: v1(1581.77,870.23) UD5.12@1689.03,870.23
  Bottom Layer w7: UT55.20@1189.63,1076.07 1226.57,1076.07 1432.4,870.23 v1(1581.77,870.23)
TRAN2_DATA14: UD5.13 UT55.22 | length 582.3
  Top Layer w7: v1(1620.1,844.63) UD5.13@1689.03,844.63
  Bottom Layer w7: UT55.22@1189.63,1044.67 1234.97,1044.67 1435,844.63 v1(1620.1,844.63)
TRAN2_DATA15: UD5.14 UT55.23 | length 586.4
  Top Layer w7: v1(1581.77,819.03) UD5.14@1689.03,819.03
  Bottom Layer w7: UT55.23@1189.63,1028.97 1230.67,1028.97 1440.6,819.03 v1(1581.77,819.03)
TRAN3_DATA0: UD9.27 UT45.2 | length 1022.3
  Top Layer w7: v1(1631.63,2824) 1631.27,2824.37 1643.63,2824.37 1654.63,2813.37 2010.63,2813.37 2027.63,2796.37 2027.63,2771.37 2002.5,2746.23 UD9.27@1964.03,2746.23
  Bottom Layer w7: UT45.2@1189.63,2999.67 1246.97,2999.67 1422.27,2824.37 1631.27,2824.37 v1(1631.63,2824)
TRAN3_DATA1: UD9.28 UT45.3 | length 870
  Top Layer w7: v1(1586.63,2797.37) 1951.63,2797.37 1964.03,2784.97 UD9.28@1964.03,2771.83
  Bottom Layer w7: UT45.3@1189.63,2983.97 1242.67,2983.97 1429.27,2797.37 v1(1586.63,2797.37)
TRAN3_DATA2: UD9.1 UT45.5 | length 579.3
  Top Layer w7: v1(1625.1,2771.83) UD9.1@1694.03,2771.83
  Bottom Layer w7: UT45.5@1189.63,2952.57 1227.83,2952.57 1228.03,2952.37 1254.27,2952.37 1434.8,2771.83 v1(1625.1,2771.83)
TRAN3_DATA3: UD9.2 UT45.6 | length 583.6
  Top Layer w7: v1(1577.63,2746) 1577.87,2746.23 UD9.2@1694.03,2746.23
  Bottom Layer w7: UT45.6@1189.63,2936.87 1249.77,2936.87 1440.4,2746.23 1577.4,2746.23 v1(1577.63,2746)
TRAN3_DATA4: UD9.3 UT45.8 | length 581
  Top Layer w7: v1(1625.1,2720.63) UD9.3@1694.03,2720.63
  Bottom Layer w7: UT45.8@1189.63,2905.47 1261.17,2905.47 1446,2720.63 v1(1625.1,2720.63)
TRAN3_DATA5: UD9.4 UT45.9 | length 587.8
  Top Layer w7: v1(1586.77,2695.03) UD9.4@1694.03,2695.03 UD9.4@1692.03,2693.17
  Bottom Layer w7: UT45.9@1189.63,2889.77 1252.87,2889.77 1447.6,2695.03 v1(1586.77,2695.03)
TRAN3_DATA6: UD9.5 UT45.11 | length 582.7
  Top Layer w7: v1(1625.1,2669.43) UD9.5@1694.03,2669.43
  Bottom Layer w7: UT45.11@1189.63,2858.37 1263.27,2858.37 1452.2,2669.43 v1(1625.1,2669.43)
TRAN3_DATA7: UD9.6 UT45.12 | length 586.8
  Top Layer w7: v1(1577.63,2644) 1577.8,2643.83 UD9.6@1694.03,2643.83
  Bottom Layer w7: UT45.12@1189.63,2842.67 1257.97,2842.67 1456.63,2644 v1(1577.63,2644)
TRAN3_DATA8: UD9.7 UT45.13 | length 590.9
  Top Layer w7: v1(1625.1,2618.23) UD9.7@1694.03,2618.23
  Bottom Layer w7: UT45.13@1189.63,2826.97 1252.67,2826.97 1461.4,2618.23 v1(1625.1,2618.23)
TRAN3_DATA9: UD9.8 UT45.14 | length 595
  Top Layer w7: v1(1586.77,2592.63) UD9.8@1694.03,2592.63
  Bottom Layer w7: UT45.14@1189.63,2811.27 1248.37,2811.27 1467,2592.63 v1(1586.77,2592.63)
TRAN3_DATA10: UD9.9 UT45.16 | length 592.6
  Top Layer w7: v1(1625.1,2567.03) UD9.9@1694.03,2567.03
  Bottom Layer w7: UT45.16@1189.63,2779.87 1258.77,2779.87 1471.6,2567.03 v1(1625.1,2567.03)
TRAN3_DATA11: UD9.10 UT45.17 | length 596.7
  Top Layer w7: v1(1586.77,2541.43) UD9.10@1694.03,2541.43
  Bottom Layer w7: UT45.17@1189.63,2764.17 1250.47,2764.17 1473.2,2541.43 v1(1586.77,2541.43)
TRAN3_DATA12: UD9.11 UT45.19 | length 594.3
  Top Layer w7: v1(1625.1,2515.83) UD9.11@1694.03,2515.83
  Bottom Layer w7: UT45.19@1189.63,2732.77 1260.87,2732.77 1477.8,2515.83 v1(1625.1,2515.83)
TRAN3_DATA13: UD9.12 UT45.20 | length 598.4
  Top Layer w7: v1(1586.77,2490.23) UD9.12@1694.03,2490.23
  Bottom Layer w7: UT45.20@1189.63,2717.07 1256.57,2717.07 1483.4,2490.23 v1(1586.77,2490.23)
TRAN3_DATA14: UD9.13 UT45.22 | length 596
  Top Layer w7: v1(1625.1,2464.63) UD9.13@1694.03,2464.63
  Bottom Layer w7: UT45.22@1189.63,2685.67 1266.97,2685.67 1488,2464.63 v1(1625.1,2464.63)
TRAN3_DATA15: UD9.14 UT45.23 | length 600.1
  Top Layer w7: v1(1577.63,2439) UD9.14@1694.03,2439.03
  Bottom Layer w7: UT45.23@1189.63,2669.97 1262.67,2669.97 1493.6,2439.03 v1(1577.63,2439)
TRAN4_DATA0: UD13.27 UT60.2 | length 992.4
  Top Layer w7: v1(1627.63,3279.37) 1648.63,3279.37 1659.63,3268.37 1997.27,3268.37 2024.63,3241 2024.63,3218.37 2007.5,3201.23 UD13.27@1969.03,3201.23
  Bottom Layer w7: UT60.2@1188.63,3412.67 1238.97,3412.67 1372.27,3279.37 v1(1627.63,3279.37)
TRAN4_DATA1: UD13.28 UT60.3 | length 858.6
  Top Layer w7: v1(1591.63,3252.37) 1956.63,3252.37 1969.03,3239.97 UD13.28@1969.03,3226.83
  Bottom Layer w7: UT60.3@1188.63,3396.97 1233.67,3396.97 1378.27,3252.37 v1(1591.63,3252.37)
TRAN4_DATA2: UD13.1 UT60.5 | length 567.9
  Top Layer w7: v1(1630.1,3226.83) UD13.1@1699.03,3226.83
  Bottom Layer w7: UT60.5@1188.63,3365.57 1243.07,3365.57 1381.8,3226.83 v1(1630.1,3226.83)
TRAN4_DATA3: UD13.2 UT60.6 | length 572
  Top Layer w7: v1(1591.77,3201.23) UD13.2@1699.03,3201.23
  Bottom Layer w7: UT60.6@1188.63,3349.87 1238.77,3349.87 1387.4,3201.23 v1(1591.77,3201.23)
